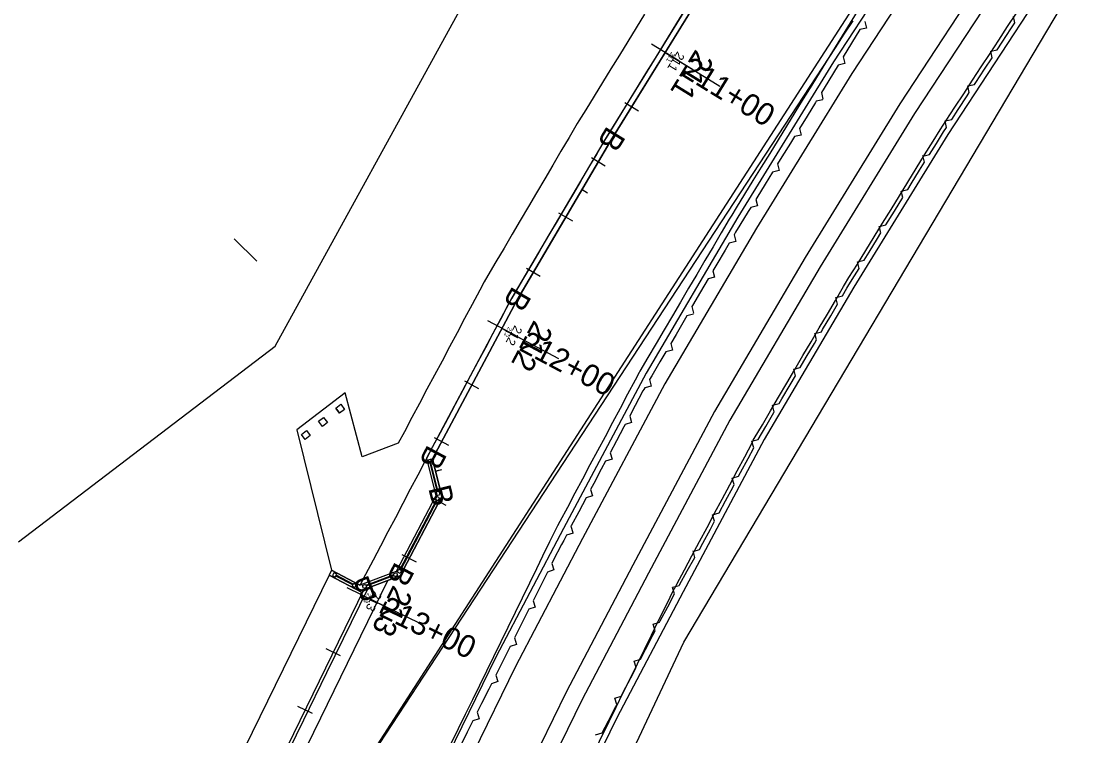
# Model space of a CAD drawing. Extents: x 1823824 to 1861612, y 706975 to 726130.
# Drawn here: x 1824482.5 to 1824817.1, y 711601.3 to 711824 of the extents above; entities that cross this region are included whole.
import ezdxf

# ---------------------------------------------------------------- set-up
doc = ezdxf.new("R2010")
doc.units = 0
for name, color, linetype in [('DR_X_Flood_Boundary', 7, 'Continuous'), ('GE_X_CL_10', 7, 'Continuous'), ('GE_X_CL_100', 7, 'Continuous'), ('GE_X_CL_20', 7, 'Continuous'), ('GE_X_CL_200', 7, 'Continuous'), ('GE_X_CL_50', 7, 'Continuous'), ('RW_X_Esmt_FL', 7, 'Continuous'), ('SC_Scratch1', 7, 'Continuous'), ('SC_Scratch3', 7, 'Continuous'), ('SC_Scratch5', 7, 'Continuous'), ('SC_Scratch6', 7, 'Continuous')]:
    doc.layers.add(name, color=color, linetype=linetype)

msp = doc.modelspace()

# ---------------------------------------------------------------- linework, layer by layer
at = {"layer": 'DR_X_Flood_Boundary'}
for p, q in [((1824696.93, 711836.18), (1824666.49, 711786.8)), ((1824666.49, 711786.8), (1824637.12, 711736.9)), ((1824637.12, 711736.9), (1824610.8, 711687.52)), ((1824610.8, 711687.52), (1824613.7, 711675.83)), ((1824613.7, 711675.83), (1824600.68, 711651.04)), ((1824600.68, 711651.04), (1824589.41, 711646.8)), ((1824589.41, 711646.8), (1824535.27, 711536.02))]:
    msp.add_line(p, q, dxfattribs=at)
at = {"layer": 'GE_X_CL_10'}
for p, q in [((1824683.43, 711814.28), (1824684.28, 711813.75)), ((1824657.5, 711771.53), (1824658.36, 711771.02)), ((1824632.5, 711728.24), (1824633.38, 711727.76)), ((1824611.73, 711683.77), (1824612.7, 711684.01)), ((1824588.63, 711645.2), (1824589.53, 711644.76))]:
    msp.add_line(p, q, dxfattribs=at)
at = {"layer": 'GE_X_CL_100'}
for p, q in [((1824683.43, 711814.28), (1824691.94, 711809.03)), ((1824632.5, 711728.24), (1824641.32, 711723.53)), ((1824588.63, 711645.2), (1824597.61, 711640.81))]:
    msp.add_line(p, q, dxfattribs=at)
at = {"layer": 'GE_X_CL_20'}
for p, q in [((1824683.43, 711814.28), (1824685.13, 711813.23)), ((1824657.5, 711771.53), (1824659.22, 711770.51)), ((1824632.5, 711728.24), (1824634.26, 711727.29)), ((1824611.73, 711683.77), (1824613.67, 711684.25)), ((1824588.63, 711645.2), (1824590.43, 711644.32))]:
    msp.add_line(p, q, dxfattribs=at)
at = {"layer": 'GE_X_CL_200'}
for p, q in [((1824683.43, 711814.28), (1824700.45, 711803.78)), ((1824632.5, 711728.24), (1824650.15, 711718.83)), ((1824588.63, 711645.2), (1824606.6, 711636.41))]:
    msp.add_line(p, q, dxfattribs=at)
at = {"layer": 'GE_X_CL_50'}
for p, q in [((1824683.43, 711814.28), (1824687.68, 711811.65)), ((1824632.5, 711728.24), (1824636.91, 711725.88)), ((1824588.63, 711645.2), (1824593.12, 711643))]:
    msp.add_line(p, q, dxfattribs=at)
at = {"layer": 'RW_X_Esmt_FL'}
for p, q in [((1824561.76, 711722.66), (1824646.86, 711877.55)), ((1824689.22, 711630.44), (1824810.57, 711834.59)), ((1824481.66, 711661.64), (1824561.76, 711722.66)), ((1824605.52, 711452.44), (1824689.22, 711630.44))]:
    msp.add_line(p, q, dxfattribs=at)
at = {"layer": 'SC_Scratch1'}
for p, q in [((1824792.53, 711823.48), (1824792.1, 711825.55)), ((1824746.2, 711821.9), (1824744.15, 711821.41)), ((1824745.71, 711823.95), (1824746.2, 711821.9)), ((1824784.98, 711814.69), (1824787.04, 711815.12)), ((1824738.93, 711812.88), (1824739.42, 711810.84)), ((1824785.41, 711812.63), (1824784.98, 711814.69)), ((1824739.42, 711810.84), (1824737.38, 711810.34)), ((1824732.16, 711801.81), (1824732.65, 711799.77)), ((1824777.87, 711803.84), (1824779.93, 711804.27)), ((1824778.3, 711801.78), (1824777.87, 711803.84)), ((1824732.61, 711799.56), (1824730.56, 711799.07)), ((1824770.75, 711792.99), (1824772.81, 711793.42)), ((1824771.18, 711790.93), (1824770.75, 711792.99)), ((1824725.8, 711788.51), (1824723.75, 711788.03)), ((1824725.31, 711790.56), (1824725.8, 711788.51)), ((1824763.85, 711781.95), (1824765.89, 711782.44)), ((1824764.33, 711780.08), (1824763.85, 711782.13)), ((1824718.5, 711779.52), (1824718.99, 711777.47)), ((1824718.99, 711777.47), (1824716.94, 711776.98)), ((1824757.03, 711771.08), (1824759.08, 711771.57)), ((1824711.69, 711768.47), (1824712.18, 711766.42)), ((1824757.52, 711769.03), (1824757.03, 711771.08)), ((1824712.18, 711766.42), (1824710.13, 711765.94)), ((1824750.22, 711760.04), (1824752.27, 711760.52)), ((1824750.71, 711757.99), (1824750.22, 711760.04)), ((1824705.43, 711755.37), (1824703.39, 711754.84)), ((1824704.9, 711757.41), (1824705.43, 711755.37)), ((1824743.41, 711748.99), (1824745.46, 711749.48)), ((1824743.9, 711746.94), (1824743.41, 711748.99)), ((1824698.32, 711746.23), (1824698.85, 711744.19)), ((1824698.85, 711744.19), (1824696.81, 711743.66)), ((1824736.69, 711737.86), (1824738.72, 711738.39)), ((1824691.74, 711735.04), (1824692.27, 711733)), ((1824737.21, 711735.82), (1824736.69, 711737.86)), ((1824692.24, 711732.64), (1824690.21, 711732.11)), ((1824730.1, 711726.67), (1824732.14, 711727.2)), ((1824730.63, 711724.64), (1824730.1, 711726.67)), ((1824685.66, 711721.45), (1824683.62, 711720.93)), ((1824685.13, 711723.49), (1824685.66, 711721.45)), ((1824723.52, 711715.49), (1824725.56, 711716.02)), ((1824724.05, 711713.45), (1824723.52, 711715.49)), ((1824678.55, 711712.31), (1824679.08, 711710.27)), ((1824679.08, 711710.27), (1824677.04, 711709.74)), ((1824582.18, 711704.57), (1824583.39, 711702.98)), ((1824716.94, 711704.31), (1824718.98, 711704.83)), ((1824580.59, 711703.36), (1824581.8, 711701.77)), ((1824717.47, 711702.27), (1824716.94, 711704.31)), ((1824672.94, 711698.91), (1824670.93, 711698.3)), ((1824672.33, 711700.92), (1824672.94, 711698.91)), ((1824710.36, 711693.12), (1824712.4, 711693.65)), ((1824711.03, 711691.01), (1824710.42, 711693.02)), ((1824666.23, 711689.47), (1824666.84, 711687.46)), ((1824666.84, 711687.46), (1824664.82, 711686.84)), ((1824704.32, 711681.57), (1824706.33, 711682.18)), ((1824704.93, 711679.55), (1824704.32, 711681.57)), ((1824660.12, 711678.02), (1824660.73, 711676.01)), ((1824660.73, 711676.01), (1824658.72, 711675.39)), ((1824698.21, 711670.12), (1824700.23, 711670.73)), ((1824698.83, 711668.1), (1824698.21, 711670.12)), ((1824654.02, 711666.57), (1824654.63, 711664.55)), ((1824654.68, 711664.37), (1824652.66, 711663.78)), ((1824692.11, 711658.66), (1824694.12, 711659.28)), ((1824692.67, 711656.81), (1824692.11, 711658.84)), ((1824648.04, 711654.91), (1824648.7, 711652.91)), ((1824648.7, 711652.91), (1824646.7, 711652.25)), ((1824685.74, 711647.53), (1824687.76, 711648.1)), ((1824686.34, 711645.48), (1824685.72, 711647.49)), ((1824642.87, 711641.32), (1824640.87, 711640.66)), ((1824642.21, 711643.32), (1824642.87, 711641.32)), ((1824679.68, 711636), (1824681.69, 711636.63)), ((1824680.32, 711633.99), (1824679.68, 711636)), ((1824636.39, 711631.72), (1824637.05, 711629.72)), ((1824637.05, 711629.72), (1824635.05, 711629.06)), ((1824673.69, 711624.48), (1824675.7, 711625.12)), ((1824674.33, 711622.48), (1824673.69, 711624.48)), ((1824631.23, 711618.12), (1824629.23, 711617.46)), ((1824630.56, 711620.12), (1824631.23, 711618.12)), ((1824667.71, 711612.97), (1824669.71, 711613.6)), ((1824668.34, 711610.96), (1824667.71, 711612.97)), ((1824624.74, 711608.53), (1824625.41, 711606.53)), ((1824625.41, 711606.53), (1824623.41, 711605.86)), ((1824661.72, 711601.46), (1824663.72, 711602.09))]:
    msp.add_line(p, q, dxfattribs=at)
for points in [[(1825105.72, 712238.1), (1825041.58, 712175.28), (1825012.05, 712142.98), (1824928.03, 712058.8), (1824867.42, 711988.62), (1824838.82, 711954.42), (1824791.58, 711892.69), (1824765.73, 711856.76), (1824735.96, 711811.35), (1824706.1, 711762.93), (1824677.47, 711714.29), (1824651.68, 711665.89), (1824630.67, 711625.89), (1824564.54, 711490.46), (1824542.7, 711439.44)], [(1825110.13, 712232.99), (1825046.42, 712170.6), (1825016.92, 712138.33), (1824932.97, 712054.22), (1824872.55, 711984.27), (1824844.08, 711950.22), (1824796.99, 711888.68), (1824771.28, 711852.95), (1824741.64, 711807.74), (1824711.87, 711759.46), (1824683.34, 711710.99), (1824657.63, 711662.75), (1824636.68, 711622.85), (1824570.66, 711487.65), (1824551.08, 711441.92)], [(1825121.76, 712219.53), (1825059.19, 712158.26), (1825029.76, 712126.06), (1824945.98, 712042.13), (1824886.07, 711972.77), (1824857.94, 711939.13), (1824811.24, 711878.1), (1824785.91, 711842.89), (1824756.62, 711798.22), (1824727.07, 711750.3), (1824698.83, 711702.31), (1824673.32, 711654.44), (1824652.51, 711614.83), (1824615.99, 711540.02)], [(1825125.32, 712215.32), (1825063.14, 712154.44), (1825033.74, 712122.26), (1824950.02, 712038.39), (1824890.27, 711969.21), (1824862.23, 711935.69), (1824815.66, 711874.82), (1824790.44, 711839.78), (1824761.26, 711795.26), (1824731.78, 711747.46), (1824703.63, 711699.63), (1824678.18, 711651.87), (1824657.42, 711612.34), (1824626.24, 711548.48)], [(1825133.34, 712206.03), (1825071.96, 712145.93), (1825042.6, 712113.8), (1824959, 712030.04), (1824899.6, 711961.27), (1824871.8, 711928.03), (1824825.5, 711867.52), (1824800.54, 711832.84), (1824771.6, 711788.69), (1824742.28, 711741.14), (1824714.32, 711693.64), (1824689.01, 711646.14), (1824668.35, 711606.81), (1824642.05, 711552.94)], [(1824741.94, 711824.13), (1824739.2, 711819.95), (1824736.46, 711815.76), (1824572.41, 711565.5), (1824785.18, 711894.95), (1824731.76, 711808.36), (1824729.14, 711804.1), (1824726.51, 711799.84), (1824723.89, 711795.59), (1824721.27, 711791.33), (1824718.64, 711787.08), (1824716.02, 711782.82), (1824713.39, 711778.56), (1824710.77, 711774.31), (1824708.14, 711770.05), (1824705.52, 711765.8), (1824704.16, 711763.59), (1824703.41, 711762.3), (1824700.87, 711757.99), (1824698.34, 711753.68), (1824695.8, 711749.37), (1824693.26, 711745.06), (1824690.73, 711740.75), (1824688.19, 711736.44), (1824685.66, 711732.13), (1824683.12, 711727.82), (1824680.58, 711723.51), (1824678.05, 711719.21), (1824675.51, 711714.9), (1824675.27, 711714.48), (1824674.06, 711712.13), (1824671.7, 711707.71), (1824669.35, 711703.3), (1824667, 711698.89), (1824664.65, 711694.48), (1824662.3, 711690.06), (1824659.94, 711685.65), (1824657.59, 711681.24), (1824655.24, 711676.83), (1824652.89, 711672.41), (1824650.54, 711668), (1824649.86, 711666.73), (1824647.36, 711661.7), (1824645.16, 711657.21), (1824643.22, 711653.26), (1824627.63, 711621.37), (1824625.44, 711616.88), (1824623.24, 711612.39), (1824621.04, 711607.9), (1824618.85, 711603.41), (1824616.65, 711598.91)], [(1824726.53, 711884.51), (1824726.46, 711884.42), (1824726.11, 711883.87), (1824723.37, 711879.69), (1824720.63, 711875.51), (1824717.88, 711871.33), (1824715.14, 711867.15), (1824712.4, 711862.97), (1824709.66, 711858.78), (1824706.92, 711854.6), (1824704.18, 711850.42), (1824701.44, 711846.24), (1824698.7, 711842.06), (1824695.95, 711837.88), (1824695.39, 711837.01), (1824693.38, 711833.75), (1824690.76, 711829.5), (1824688.13, 711825.24), (1824685.51, 711820.99), (1824682.88, 711816.73)], [(1824677, 711826.23), (1824674.37, 711821.98), (1824671.75, 711817.72), (1824669.12, 711813.47), (1824666.5, 711809.21), (1824663.87, 711804.95), (1824661.25, 711800.7), (1824658.62, 711796.44), (1824656.48, 711792.96), (1824655.96, 711792.09), (1824653.43, 711787.78), (1824650.89, 711783.47), (1824648.36, 711779.16), (1824645.82, 711774.85), (1824643.28, 711770.54), (1824640.75, 711766.23), (1824638.21, 711761.92), (1824635.68, 711757.62), (1824633.14, 711753.31), (1824630.6, 711749), (1824628.07, 711744.69), (1824626.92, 711742.73), (1824625.53, 711740.14), (1824623.18, 711735.72), (1824620.83, 711731.31), (1824618.48, 711726.9), (1824616.13, 711722.48), (1824613.78, 711718.07), (1824611.43, 711713.66), (1824609.07, 711709.25), (1824606.72, 711704.83), (1824604.37, 711700.42), (1824602.02, 711696.01), (1824600.13, 711692.45), (1824588.82, 711688.15), (1824583.6, 711708.14), (1824568.46, 711696.6), (1824579.32, 711652.85)], [(1824767, 711786.63), (1824769.21, 711790.2), (1824771.09, 711793.07), (1824773.83, 711797.25), (1824776.57, 711801.43), (1824779.31, 711805.61), (1824782.05, 711809.79), (1824784.79, 711813.97), (1824787.53, 711818.16), (1824790.27, 711822.34), (1824793.02, 711826.52)], [(1824787.04, 711815.12), (1824788.58, 711817.46), (1824791.32, 711821.64), (1824792.53, 711823.48)], [(1824744.15, 711821.41), (1824738.93, 711812.88)], [(1824682.88, 711816.73), (1824680.26, 711812.47), (1824677.63, 711808.22), (1824675.01, 711803.96), (1824672.39, 711799.71), (1824669.76, 711795.45), (1824667.14, 711791.19), (1824664.99, 711787.71), (1824664.58, 711787.02), (1824662.05, 711782.71), (1824659.51, 711778.4), (1824656.97, 711774.09), (1824654.44, 711769.78), (1824651.9, 711765.47), (1824649.37, 711761.16), (1824646.83, 711756.85), (1824644.29, 711752.54), (1824641.76, 711748.23), (1824639.22, 711743.93), (1824636.69, 711739.62), (1824635.53, 711737.66), (1824634.35, 711735.44), (1824632, 711731.02), (1824629.65, 711726.61), (1824627.3, 711722.2), (1824624.95, 711717.78), (1824622.6, 711713.37), (1824620.25, 711708.96), (1824617.9, 711704.54), (1824615.55, 711700.13), (1824613.2, 711695.72), (1824610.85, 711691.31), (1824608.5, 711686.89), (1824608.33, 711686.57), (1824606.18, 711682.49), (1824603.86, 711678.07), (1824601.54, 711673.64), (1824599.21, 711669.21), (1824596.89, 711664.79), (1824594.56, 711660.36), (1824592.24, 711655.93), (1824589.91, 711651.51), (1824588.31, 711648.47), (1824588.17, 711648.2)], [(1824779.93, 711804.27), (1824780.35, 711804.91), (1824783.09, 711809.1), (1824785.41, 711812.63)], [(1824737.38, 711810.34), (1824733, 711803.19), (1824732.16, 711801.81)], [(1824772.81, 711793.42), (1824774.87, 711796.55), (1824777.61, 711800.73), (1824778.3, 711801.78)], [(1824730.56, 711799.07), (1824730.35, 711798.72), (1824727.72, 711794.47), (1824725.31, 711790.56)], [(1824765.89, 711782.44), (1824768.05, 711785.93), (1824770.25, 711789.51), (1824771.18, 711790.93)], [(1824626.65, 711525.69), (1824665.92, 711605.67), (1824668.12, 711610.16), (1824670.33, 711614.66), (1824672.54, 711619.15), (1824674.74, 711623.64), (1824676.95, 711628.14), (1824679.16, 711632.63), (1824681.36, 711637.12), (1824683.57, 711641.62), (1824686.37, 711647.21), (1824686.38, 711647.23), (1824687.07, 711648.53), (1824689.43, 711652.94), (1824691.78, 711657.35), (1824694.13, 711661.77), (1824696.48, 711666.18), (1824698.83, 711670.59), (1824701.18, 711675), (1824703.54, 711679.42), (1824705.89, 711683.83), (1824708.24, 711688.24), (1824710.57, 711692.61), (1824710.9, 711693.4), (1824711.19, 711693.9), (1824713.73, 711698.21), (1824716.26, 711702.52), (1824718.8, 711706.82), (1824721.33, 711711.13), (1824723.87, 711715.44), (1824726.41, 711719.75), (1824728.94, 711724.06), (1824731.48, 711728.37), (1824734.01, 711732.68), (1824736.55, 711736.99), (1824739.08, 711741.28), (1824739.38, 711741.83), (1824740.76, 711744.07), (1824743.38, 711748.32), (1824746.01, 711752.58), (1824748.63, 711756.83), (1824751.26, 711761.09), (1824753.88, 711765.35), (1824756.5, 711769.6), (1824759.13, 711773.86), (1824761.75, 711778.11), (1824764.38, 711782.37), (1824767, 711786.63)], [(1824723.75, 711788.03), (1824722.47, 711785.96), (1824719.85, 711781.7), (1824718.5, 711779.52)], [(1824759.08, 711771.57), (1824760.17, 711773.33), (1824762.8, 711777.59), (1824764.33, 711780.08)], [(1824716.94, 711776.98), (1824714.6, 711773.19), (1824711.98, 711768.93), (1824711.69, 711768.47)], [(1824752.27, 711760.52), (1824752.3, 711760.57), (1824754.92, 711764.82), (1824757.52, 711769.03)], [(1824710.13, 711765.94), (1824709.35, 711764.68), (1824706.73, 711760.42), (1824705.37, 711758.21), (1824704.9, 711757.41)], [(1824555.96, 711749.25), (1824548.92, 711756.19)], [(1824703.39, 711754.84), (1824702.08, 711752.61), (1824699.55, 711748.3), (1824698.32, 711746.23)], [(1824745.46, 711749.48), (1824747.05, 711752.06), (1824749.67, 711756.31), (1824750.71, 711757.99)], [(1824738.72, 711738.39), (1824740.12, 711740.76), (1824740.42, 711741.3), (1824741.8, 711743.54), (1824743.9, 711746.94)], [(1824696.81, 711743.66), (1824694.47, 711739.68), (1824691.94, 711735.38), (1824691.74, 711735.04)], [(1824732.14, 711727.2), (1824732.52, 711727.85), (1824735.06, 711732.16), (1824737.21, 711735.82)], [(1824690.21, 711732.11), (1824689.38, 711730.7), (1824686.84, 711726.39), (1824685.13, 711723.49)], [(1824725.56, 711716.02), (1824727.45, 711719.23), (1824729.99, 711723.54), (1824730.63, 711724.64)], [(1824683.62, 711720.93), (1824681.77, 711717.77), (1824679.23, 711713.46), (1824678.55, 711712.31)], [(1824718.98, 711704.83), (1824719.84, 711706.3), (1824722.38, 711710.61), (1824724.05, 711713.45)], [(1824677.04, 711709.74), (1824676.7, 711709.16), (1824676.45, 711708.74), (1824675.24, 711706.39), (1824672.89, 711701.97), (1824672.33, 711700.92)], [(1824712.4, 711693.65), (1824714.77, 711697.68), (1824717.31, 711701.99), (1824717.47, 711702.27)], [(1824670.93, 711698.3), (1824670.54, 711697.56), (1824668.18, 711693.15), (1824666.23, 711689.47)], [(1824706.33, 711682.18), (1824706.93, 711683.31), (1824709.28, 711687.72), (1824711.03, 711691.01)], [(1824664.82, 711686.84), (1824663.48, 711684.32), (1824661.13, 711679.91), (1824660.12, 711678.02)], [(1824700.23, 711670.73), (1824702.23, 711674.48), (1824704.58, 711678.89), (1824704.93, 711679.55)], [(1824658.72, 711675.39), (1824656.43, 711671.09), (1824654.07, 711666.67), (1824654.02, 711666.57)], [(1824694.12, 711659.28), (1824695.17, 711661.24), (1824697.52, 711665.66), (1824698.83, 711668.1)], [(1824652.66, 711663.78), (1824651.75, 711662.11), (1824651.06, 711660.84), (1824648.51, 711655.84), (1824648.04, 711654.91)], [(1824687.76, 711648.1), (1824687.86, 711648.27), (1824690.32, 711652.63), (1824692.67, 711656.81)], [(1824527.53, 711515.37), (1824536.18, 711535.58), (1824536.18, 711535.58), (1824543.71, 711551), (1824550.79, 711565.51), (1824554.97, 711574.06), (1824563.89, 711592.34), (1824570.67, 711606.23), (1824577.83, 711620.9), (1824590.72, 711647.29), (1824589.41, 711646.8), (1824588.91, 711645.84), (1824578.51, 711651.3), (1824547.37, 711587.57)], [(1824646.7, 711652.25), (1824646.25, 711651.37), (1824644.28, 711647.44), (1824642.21, 711643.32)], [(1824530.46, 711510.76), (1824540.26, 711533.7), (1824596.86, 711649.6), (1824590.72, 711647.29)], [(1824681.69, 711636.63), (1824681.89, 711637.01), (1824684.2, 711641.45), (1824686.34, 711645.48)], [(1824640.87, 711640.66), (1824636.39, 711631.72)], [(1824675.7, 711625.12), (1824677.27, 711628.12), (1824679.58, 711632.56), (1824680.32, 711633.99)], [(1824635.05, 711629.06), (1824630.56, 711620.12)], [(1824669.71, 711613.6), (1824670.33, 711614.8), (1824672.65, 711619.24), (1824674.33, 711622.48)], [(1824629.23, 711617.46), (1824628.35, 711615.72), (1824626.11, 711611.25), (1824624.74, 711608.53)], [(1824663.72, 711602.09), (1824665.71, 711605.92), (1824668.02, 711610.36), (1824668.34, 711610.96)], [(1824623.41, 711605.86), (1824621.63, 711602.31), (1824619.39, 711597.85), (1824618.92, 711596.93)]]:
    msp.add_lwpolyline(points, dxfattribs=at)
for points in [[(1824582.18, 711704.57), (1824583.39, 711702.98), (1824581.8, 711701.77), (1824580.59, 711703.35)], [(1824576.82, 711700.49), (1824578.04, 711698.9), (1824576.45, 711697.69), (1824575.23, 711699.28)], [(1824571.47, 711696.41), (1824572.68, 711694.82), (1824571.09, 711693.6), (1824569.88, 711695.19)]]:
    msp.add_lwpolyline(points, close=True, dxfattribs=at)
at = {"layer": 'SC_Scratch3'}
for p, q in [((1824611.98, 711689.73), (1824610.44, 711690.54)), ((1824610.44, 711687.43), (1824609.47, 711687.19)), ((1824609.47, 711687.19), (1824609.71, 711686.22)), ((1824609.71, 711686.22), (1824610.68, 711686.46)), ((1824612.32, 711677.24), (1824610.07, 711686.31)), ((1824612.56, 711677.3), (1824610.31, 711686.37)), ((1824610.68, 711686.46), (1824610.44, 711687.43)), ((1824612.02, 711674.79), (1824600.59, 711653.02)), ((1824612.24, 711674.68), (1824600.81, 711652.9)), ((1824612.16, 711675.85), (1824611.69, 711674.97)), ((1824611.69, 711674.97), (1824612.58, 711674.5)), ((1824612.93, 711677.4), (1824611.96, 711677.15)), ((1824611.96, 711677.15), (1824612.2, 711676.18)), ((1824613.04, 711675.39), (1824612.16, 711675.85)), ((1824612.2, 711676.18), (1824613.17, 711676.42)), ((1824612.58, 711674.5), (1824613.04, 711675.39)), ((1824613.17, 711676.42), (1824612.93, 711677.4)), ((1824608.35, 711667.25), (1824608.12, 711667.37)), ((1824608.42, 711667.4), (1824608.2, 711667.52)), ((1824604.63, 711660.17), (1824604.41, 711660.29)), ((1824604.7, 711660.32), (1824604.48, 711660.43)), ((1824579.32, 711652.85), (1824588.17, 711648.2)), ((1824580.03, 711652.05), (1824579.57, 711651.17)), ((1824579.57, 711651.17), (1824580.45, 711650.7)), ((1824580.92, 711651.59), (1824580.03, 711652.05)), ((1824580.45, 711650.7), (1824580.92, 711651.59)), ((1824585.94, 711648.24), (1824580.62, 711651.03)), ((1824586.05, 711648.47), (1824580.74, 711651.26)), ((1824598.74, 711651.38), (1824590, 711648.08)), ((1824598.82, 711651.15), (1824590.09, 711647.85)), ((1824598.6, 711651.73), (1824599.54, 711652.09)), ((1824598.96, 711650.8), (1824598.6, 711651.73)), ((1824599.89, 711651.15), (1824598.96, 711650.8)), ((1824599.54, 711652.09), (1824599.89, 711651.15)), ((1824599.79, 711652.31), (1824600.25, 711653.19)), ((1824600.67, 711651.84), (1824599.79, 711652.31)), ((1824600.25, 711653.19), (1824601.14, 711652.73)), ((1824601.14, 711652.73), (1824600.67, 711651.84)), ((1824585.76, 711647.91), (1824586.23, 711648.8)), ((1824586.65, 711647.45), (1824585.76, 711647.91)), ((1824586.23, 711648.8), (1824587.11, 711648.33)), ((1824587.11, 711648.33), (1824586.65, 711647.45)), ((1824588.93, 711648.08), (1824589.86, 711648.44)), ((1824589.28, 711647.15), (1824588.93, 711648.08)), ((1824589.86, 711648.44), (1824590.22, 711647.5)), ((1824590.22, 711647.5), (1824589.28, 711647.15))]:
    msp.add_line(p, q, dxfattribs=at)
msp.add_lwpolyline([(1824695.45, 711837.1), (1824665, 711787.73), (1824635.58, 711737.75), (1824608.94, 711687.73), (1824611.84, 711676.06), (1824599.44, 711652.45), (1824588.17, 711648.2), (1824579.32, 711652.85), (1824578.51, 711651.3), (1824588.91, 711645.84), (1824589.41, 711646.8), (1824600.68, 711651.04), (1824613.7, 711675.83), (1824610.8, 711687.52), (1824637.12, 711736.9), (1824666.49, 711786.8), (1824696.93, 711836.18)], dxfattribs=at)
at = {"layer": 'SC_Scratch5'}
for points in [[(1824687.68, 711811.65), (1824679.17, 711816.9)], [(1824675.06, 711795.94), (1824670.8, 711798.57)], [(1824664.72, 711778.88), (1824660.41, 711781.42)], [(1824654.58, 711761.64), (1824650.27, 711764.18)], [(1824644.44, 711744.41), (1824640.13, 711746.94)], [(1824636.91, 711725.88), (1824628.09, 711730.59)], [(1824625.3, 711709.41), (1824620.89, 711711.76)], [(1824615.89, 711691.76), (1824611.48, 711694.11)], [(1824615.06, 711673.06), (1824610.64, 711675.38)], [(1824605.77, 711655.35), (1824601.34, 711657.68)], [(1824593.12, 711643), (1824584.14, 711647.39)], [(1824582.09, 711626.13), (1824577.6, 711628.33)], [(1824573.31, 711608.16), (1824568.82, 711610.36)]]:
    msp.add_lwpolyline(points, dxfattribs=at)

# ---------------------------------------------------------------- texts
at = {"layer": 'GE_X_CL_10'}
for s, rotation, p in [('211', 238.3405, (1824685.34, 711814.52)), ('212', 241.9438, (1824634.5, 711728.81)), ('213', 243.9526, (1824590.62, 711645.85))]:
    msp.add_text(s, height=1.4, rotation=rotation, dxfattribs=at).set_placement(p)
at = {"layer": 'GE_X_CL_20'}
for s, rotation, p in [('211', 238.3405, (1824687.26, 711814.77)), ('212', 241.9438, (1824636.51, 711729.38)), ('213', 243.9526, (1824592.61, 711646.51))]:
    msp.add_text(s, height=2.8, rotation=rotation, dxfattribs=at).set_placement(p)
at = {"layer": 'GE_X_CL_50'}
for s, rotation, p in [('211', 238.3405, (1824693, 711815.52)), ('212', 241.9438, (1824642.53, 711731.1)), ('213', 243.9526, (1824598.59, 711648.49))]:
    msp.add_text(s, height=7, rotation=rotation, dxfattribs=at).set_placement(p)
at = {"layer": 'SC_Scratch5'}
for s, rotation, p in [('211+00', 328.3405, (1824687.98, 711807.36)), ('212+00', 331.9438, (1824637.47, 711721.62)), ('213+00', 333.9526, (1824593.83, 711638.76))]:
    msp.add_text(s, height=7, rotation=rotation, dxfattribs=at).set_placement(p)
at = {"layer": 'SC_Scratch6'}
for rotation, p in [(238.3405, (1824665.35, 711791.62)), (239.5214, (1824635.88, 711741.69)), (241.9438, (1824609.36, 711692.26)), (283.9289, (1824609.46, 711678.39)), (242.2927, (1824599.21, 711655.77)), (200.6563, (1824591.45, 711651.31))]:
    msp.add_text('B', height=7, rotation=rotation, dxfattribs=at).set_placement(p)

doc.saveas('drawing.dxf')
